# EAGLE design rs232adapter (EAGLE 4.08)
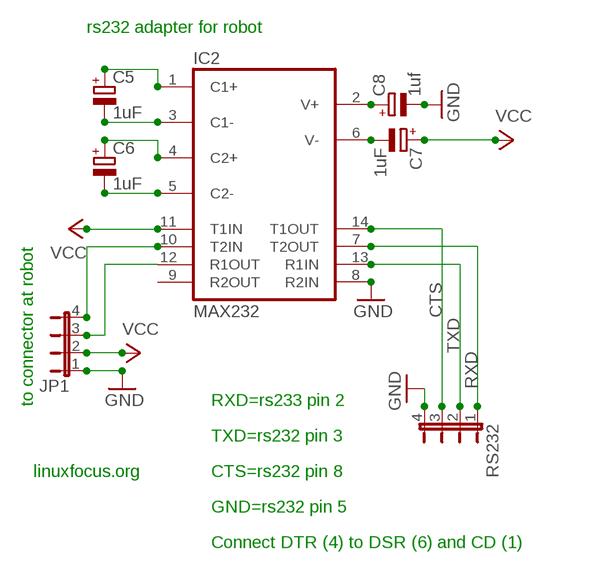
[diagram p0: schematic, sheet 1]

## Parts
C5  1uF  CPOL-EUE2.5-6  [E2,5-6]
C6  1uF  CPOL-EUE2.5-6  [E2,5-6]
C7  1uF  CPOL-EUE2.5-7  [E2,5-7]
C8  1uf  CPOL-EUE2.5-6  [E2,5-6]
IC2  MAX232  [DIL16]
JP1  JP4E  [JP4]
RS232  JP4E  [JP4]

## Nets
CTS: IC2.14(T1OUT) RS232.3
GND: C8.- IC2.8(R2IN) JP1.1 RS232.4
N$1: IC2.12(R1OUT) JP1.3
N$25: C6.- IC2.5(C2-)
N$26: C6.+ IC2.4(C2+)
N$27: C7.- IC2.6(V-)
N$28: C8.+ IC2.2(V+)
N$29: C5.- IC2.3(C1-)
N$30: C5.+ IC2.1(C1+)
N$31: IC2.10(T2IN) JP1.4
RXD: IC2.7(T2OUT) RS232.1
TXD: IC2.13(R1IN) RS232.2
VCC: C7.+ IC2.11(T1IN) JP1.2
Unconnected: IC2.9(R2OUT)

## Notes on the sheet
- rs232 adapter for robot
- to connector at robot | RXD=rs233 pin 2
- TXD=rs232 pin 3
- linuxfocus.org | CTS=rs232 pin 8
- GND=rs232 pin 5
- Connect DTR (4) to DSR (6) and CD (1)

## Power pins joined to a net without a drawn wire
GND: IC2.15(GND)
VCC: IC2.16(VCC)

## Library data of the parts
C5-C8 = rcl:CPOL-EU: POLARIZED CAPACITOR, European symbol
IC2 = maxim:MAX232: RS232 TRANSEIVER
JP1 RS232 = jumper:JP4E: JUMPER

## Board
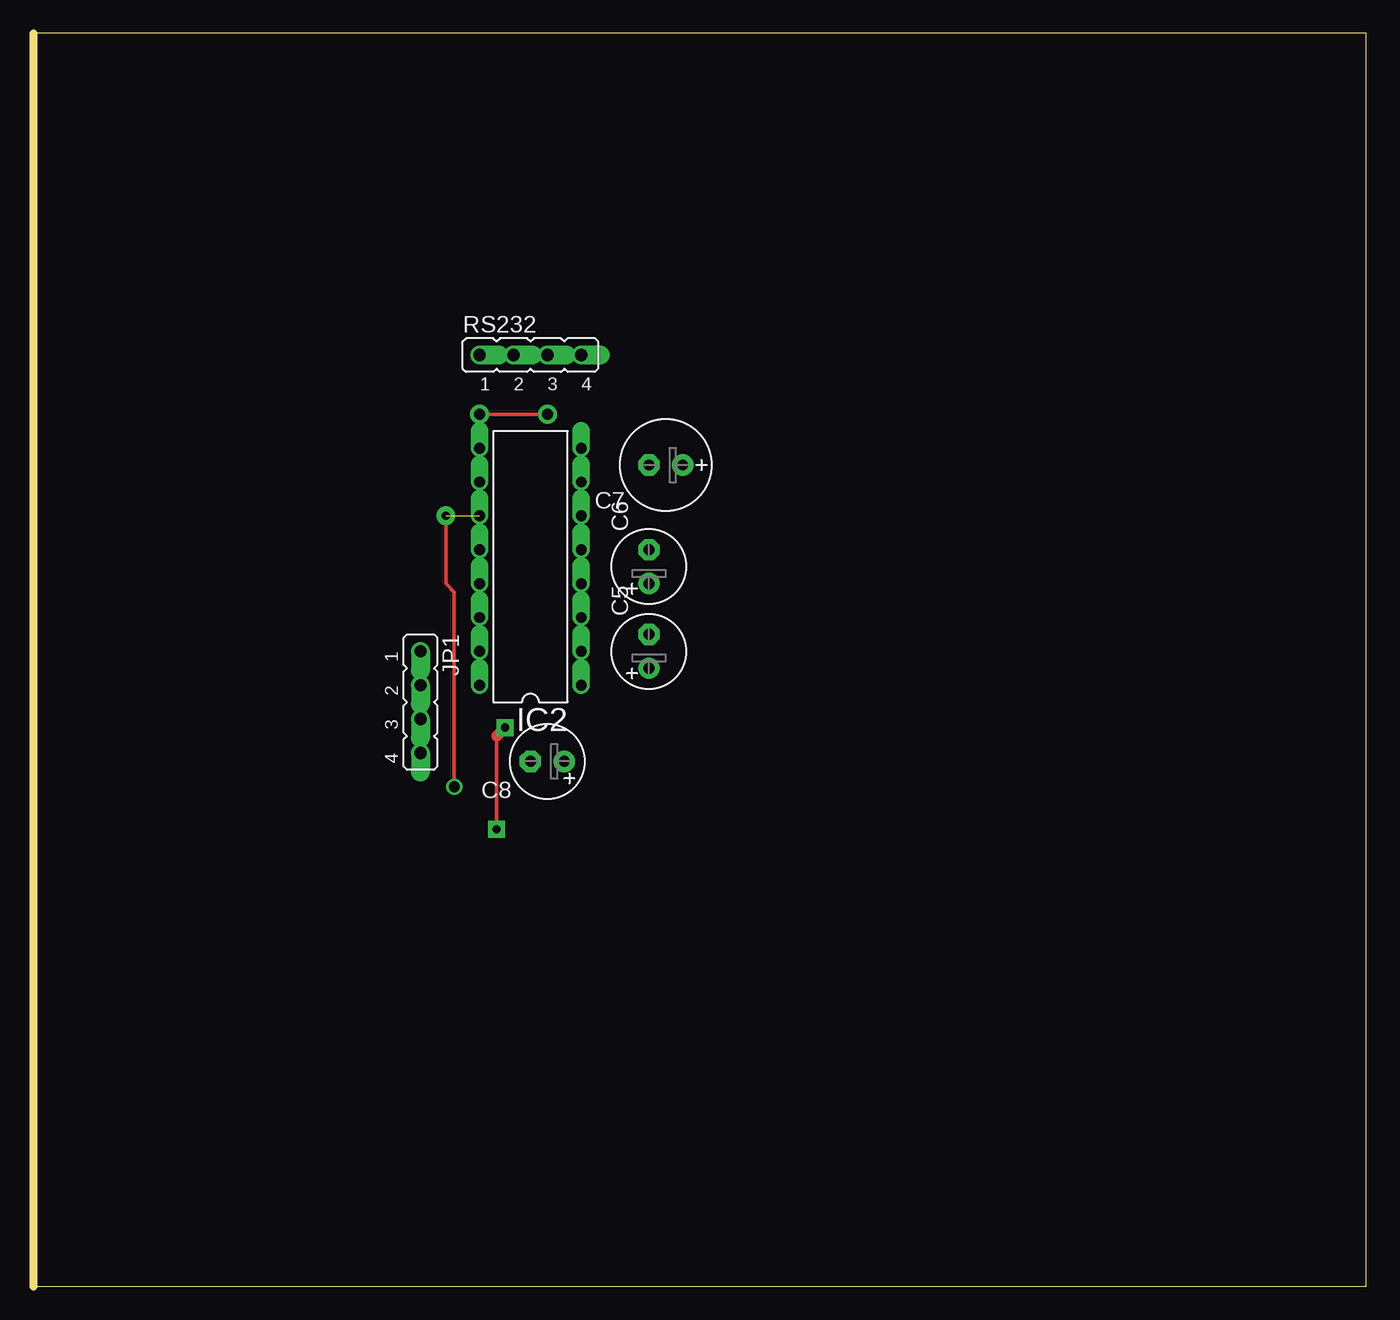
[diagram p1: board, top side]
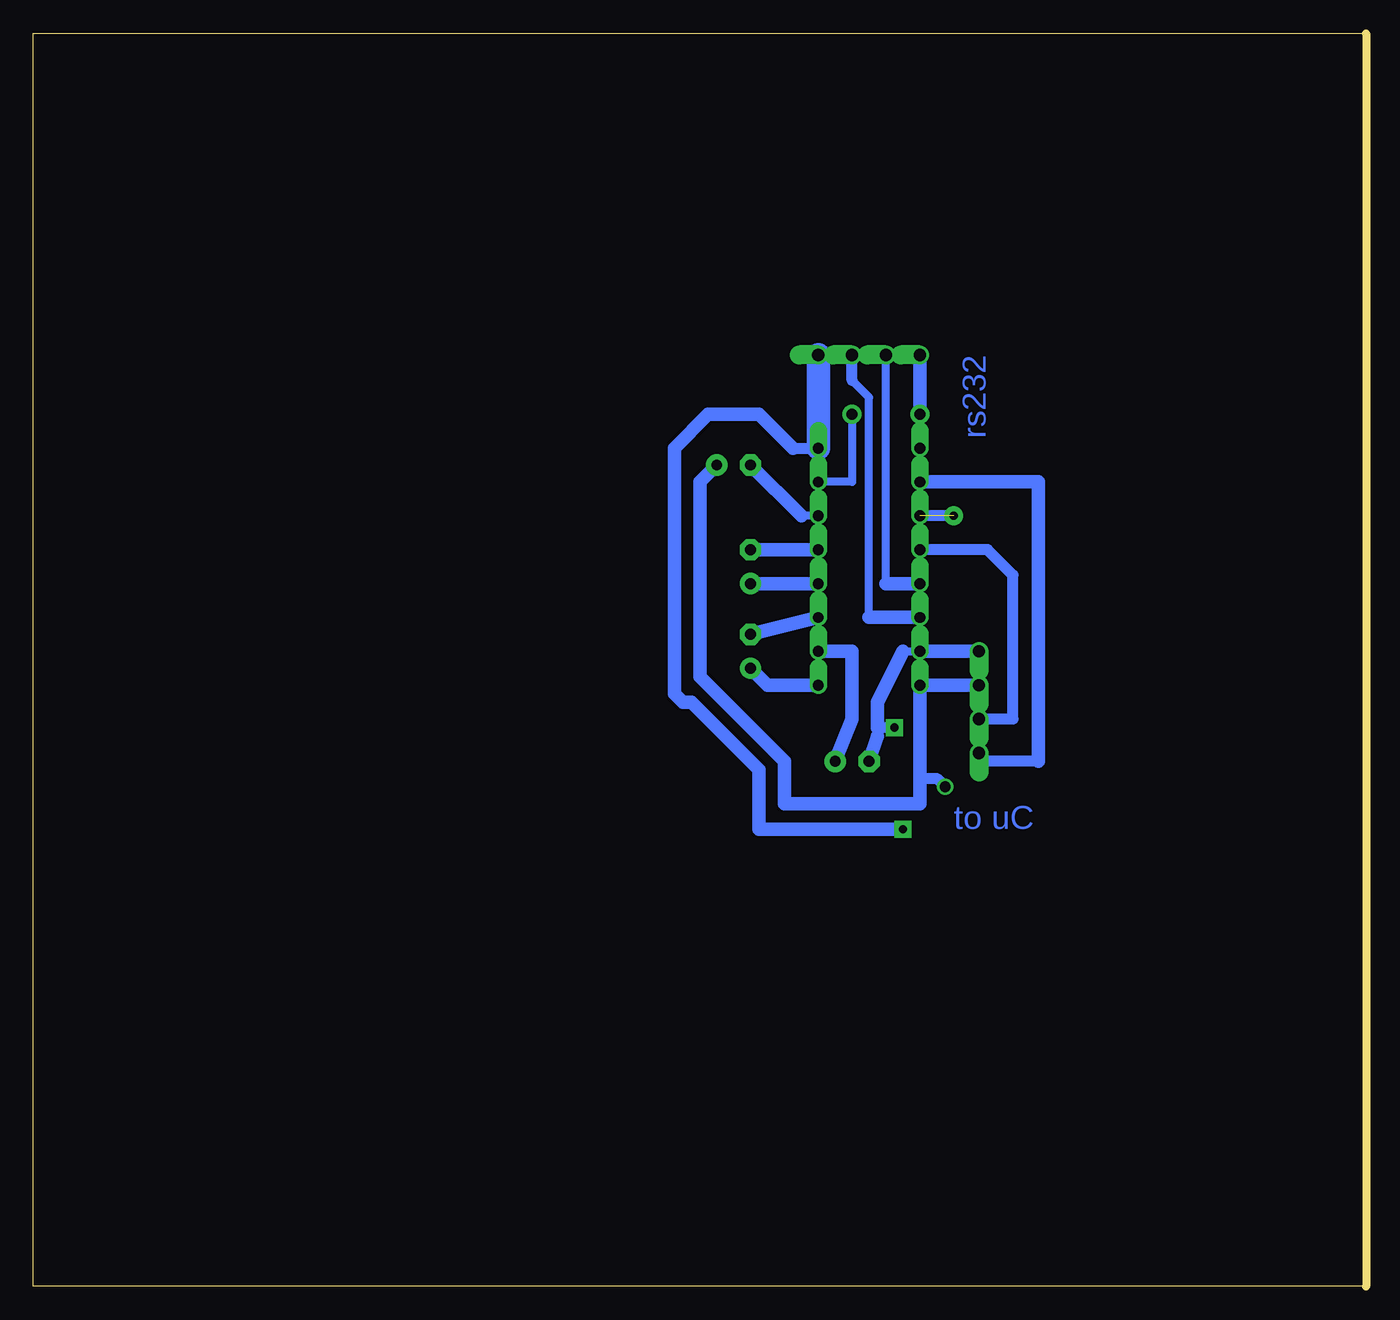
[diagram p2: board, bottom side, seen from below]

Size 100 x 93.97 mm. Coordinates in mm from the lower left corner, seen from the top.
Outline: 0,0 100,0 100,93.97 0,93.97 0,0
Copper layers used: Top, Bottom

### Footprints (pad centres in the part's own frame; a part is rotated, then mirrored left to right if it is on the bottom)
E2,5-6 = drill 0.813 pad 1.6 round: + -1.27,0 | drill 0.813 pad 1.6 octagon: - 1.27,0
E2,5-7 = drill 0.813 pad 1.6 round: + -1.27,0 | drill 0.813 pad 1.6 octagon: - 1.27,0
DIL16 = drill 0.813 offset: 1 -8.89,-3.81; 2 -6.35,-3.81; 3 -3.81,-3.81; 4 -1.27,-3.81; 5 1.27,-3.81; 6 3.81,-3.81; 7 6.35,-3.81; 8 8.89,-3.81; 9 8.89,3.81; 10 6.35,3.81; 11 3.81,3.81; 12 1.27,3.81; 13 -1.27,3.81; 14 -3.81,3.81; 15 -6.35,3.81; 16 -8.89,3.81
JP4 = drill 0.914 offset: 1 -3.81,0; 2 -1.27,0; 3 1.27,0; 4 3.81,0

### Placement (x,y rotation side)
C5  46.19,47.62 90 top
C6  46.19,53.97 90 top
C7  47.46,61.59 180 top
C8  38.57,39.36 180 top
IC2  37.3,53.97 90 top
JP1  29.04,43.81 270 top
RS232  37.3,69.84 0 top

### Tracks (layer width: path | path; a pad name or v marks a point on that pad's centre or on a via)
CTS
  Bottom 0.61: 37.3,50.16 37.3,66.67 38.57,67.94
  Bottom 0.813: 38.57,67.94 RS232.3
  Bottom 1.016: IC2.14 37.3,50.16
GND  (via drill 0.61 pad 1.27)
  Top 0.254: v34.76,34.28 34.76,41.27
  Top 0.813: 34.76,41.27 v35.39,41.91
  Bottom 0.61: 34.76,47.62 IC2.15 | IC2.8 42.38,62.86
  Bottom 0.813: 36.66,41.27 36.66,41.91 v35.39,41.91 | 43.02,62.86 IC2.8
  Bottom 1.016: 36.66,41.27 C8.- | 36.66,41.91 36.66,43.81 34.76,47.62 | IC2.15 JP1.1 | 43.02,62.86 45.55,65.4 49.37,65.4 51.91,62.86 51.91,44.45 51.27,43.81 50.63,43.81 45.55,38.73 45.55,34.28 v34.76,34.28
  Bottom 1.778: IC2.8 RS232.4
N$1
  Bottom 0.813: JP1.3 26.5,42.54 26.5,53.33 28.41,55.24 IC2.12
N$25
  Bottom 1.016: IC2.5 C6.-
N$26
  Bottom 1.016: IC2.4 C6.+
N$27
  Bottom 0.61: IC2.6 42.38,57.78
  Bottom 1.016: 42.38,57.78 C7.-
N$28
  Bottom 1.016: C8.+ 38.57,42.54 38.57,47.62 IC2.2
N$29
  Bottom 1.016: IC2.3 C5.-
N$30
  Bottom 1.016: IC2.1 44.92,45.08 C5.+
N$31
  Bottom 0.813: 24.6,39.36 29.04,39.36 JP1.4
  Bottom 1.016: IC2.10 24.6,60.32 24.6,39.36
RXD  (via drill 0.81 pad 1.42)
  Top 0.254: v33.49,65.4 v38.57,65.4
  Bottom 0.61: v38.57,65.4 38.57,60.32 IC2.7
  Bottom 1.016: v33.49,65.4 RS232.1
TXD
  Bottom 0.61: 36.03,52.7 RS232.2
  Bottom 1.016: IC2.13 36.03,52.7
VCC  (via drill 0.61 pad 1.42, 0.81 pad 0.81)  (1 unrouted)
  Top 0.254: v31.58,37.46 31.58,52.06 30.95,52.7 v30.95,57.78
  Bottom 0.813: v30.95,57.78 IC2.11 | 33.49,38.09 32.22,38.09 v31.58,37.46
  Bottom 1.016: JP1.2 IC2.16 33.49,38.09 33.49,36.19 43.65,36.19 43.65,39.36 50,45.72 50,60.32 C7.+

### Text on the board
Bottom: rs232 | to uC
